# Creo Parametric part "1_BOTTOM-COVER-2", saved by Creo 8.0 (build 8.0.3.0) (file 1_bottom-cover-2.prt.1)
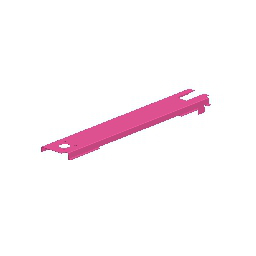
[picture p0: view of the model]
Units: millimeter Newton Second (mmNs); MM, TONNE, SECS

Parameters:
  MERGE_BASE_PART = "1_BOTTOM-COVER"
  SMT_DFLT_BEND_REL_LENGTH_TYPE = "Through All"

Other parameters: SMT_PART_BEND_ALLOWANCE_FACTOR, SMT_DFLT_BEND_RADIUS, SMT_DFLT_BEND_ANGLE, SMT_DFLT_CRNR_REL_WIDTH, SMT_DFLT_CRNR_REL_DEPTH, SMT_DFLT_BEND_REL_WIDTH, SMT_DFLT_BEND_REL_DEPTH, SMT_DFLT_BEND_REL_LENGTH, SMT_DFLT_BEND_REL_ANGLE, SMT_GAP, SMT_DFLT_EDGE_TREA_WIDTH, SMT_DFLT_MITER_CUT_WIDTH, SMT_DFLT_MITER_CUT_OFFSET

Layers: 0_ALL_AXIS, 0_ALL_CSYS, 0_ALL_CURVES, 0_ALL_PLANES, 0_ALL_POINTS, 0_ALL_SURFS, BOTTOM-COVER, BOTTOM-COVER-2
